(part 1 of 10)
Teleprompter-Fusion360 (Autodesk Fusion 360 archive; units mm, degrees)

design "Teleprompter-Multi" references "Logitech-Brio", "TV-Adapter", "Desklab-Screen"
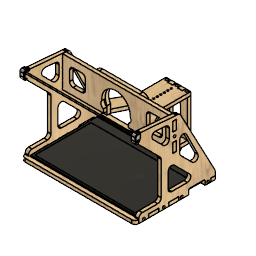
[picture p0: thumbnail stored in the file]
parameter "d305" = 2.5
component_insert "Komponente einfügen1"
position "Position1"
sketch "Skizze1" plane through (0, 0, 0) normal (0, 0, 1) x axis (1, 0, 0)
  dimension "d3" = 15
  dimension "d4" = 15
  dimension "d5" = 15
  dimension "d6" = 30
extrude "Extrusion1" new body sketch "Skizze1" along normal blind 12
sketch "Skizze2" plane through (0, 0, 12) normal (0, 0, 1) x axis (-1, 0, 0)
  line L1 (14.9969, 18.6596) -> (14.9969, -255.3404)
  line L2 (-374.0031, 18.6596) -> (14.9969, 18.6596)
  line L3 (-374.0031, -255.3404) -> (-374.0031, 18.6596)
  line L4 (14.9969, -255.3404) -> (-374.0031, -255.3404)
  line L5 (-3.5031, -225.3404) -> (-355.5031, -225.3404)
  line L6 (-0.0031, 0.1596) -> (-0.0031, -221.8404)
  line L7 (-359.0031, -221.8404) -> (-359.0031, 0.1596)
  line L8 (-355.5031, 3.6596) -> (-3.5031, 3.6596)
  line L9 (-359.0031, -150.3404) -> (-0.0031, -150.3404)
  line L10 (-358.2031, -150.3404) -> (-359.0031, -150.3404)
  line L11 (-0.8031, -150.3404) -> (-358.2031, -150.3404)
  line L12 (-0.0031, -150.3404) -> (-0.8031, -150.3404)
  line L13 (0.9969, 0.1596) -> (0.9969, -221.8404)
  line L14 (-355.5031, 4.6596) -> (-3.5031, 4.6596)
  line L15 (-360.0031, -221.8404) -> (-360.0031, 0.1596)
  line L16 (-3.5031, -226.3404) -> (-355.5031, -226.3404)
  line L17 (-0.0031, -150.3404) -> (-360.0031, -150.3404)
  arc A1 centre (-3.5031, -221.8404) radius 3.5 clockwise from (-0.0031, -221.8404) to (-3.5031, -225.3404)
  arc A2 centre (-355.5031, 0.1596) radius 3.5 clockwise from (-359.0031, 0.1596) to (-355.5031, 3.6596)
  arc A3 centre (-3.5031, 0.1596) radius 3.5 clockwise from (-3.5031, 3.6596) to (-0.0031, 0.1596)
  arc A4 centre (-355.5031, -221.8404) radius 3.5 clockwise from (-355.5031, -225.3404) to (-359.0031, -221.8404)
  arc A5 centre (-3.5031, 0.1596) radius 4.5 clockwise from (-3.5031, 4.6596) to (0.9969, 0.1596)
  arc A6 centre (-355.5031, 0.1596) radius 4.5 clockwise from (-360.0031, 0.1596) to (-355.5031, 4.6596)
  arc A7 centre (-355.5031, -221.8404) radius 4.5 clockwise from (-355.5031, -226.3404) to (-360.0031, -221.8404)
  arc A8 centre (-3.5031, -221.8404) radius 4.5 clockwise from (0.9969, -221.8404) to (-3.5031, -226.3404)
  point P26 (-0.0031, -150.3404)
  point P42 (-0.0031, -150.3404)
  point P43 (-360.0031, -150.3404)
  coincident P26 P42
  coincident L15 P43
  dimension "d7" = 1
extrude "Extrusion2" cut sketch "Skizze2" profile of A1 L5 L6 A2 L7 L8 A3 A4 L9 L10 L11 L12 L13 A5 L14 A6 L16 L15 A7 A8 L17 against normal blind 3
sketch "Skizze3" plane through (0, 0, 9) normal (0, 0, 1) x axis (-1, 0, 0)
  line L1 (-359.0031, -150.3404) -> (-0.0031, -150.3404)
  line L2 (-358.2031, -150.3404) -> (-359.0031, -150.3404)
  line L3 (-0.8031, -150.3404) -> (-358.2031, -150.3404)
  line L4 (-0.0031, -150.3404) -> (-0.8031, -150.3404)
  line L5 (0.9969, 0.1596) -> (0.9969, -221.8404)
  line L6 (-355.5031, 4.6596) -> (-3.5031, 4.6596)
  line L7 (-360.0031, -221.8404) -> (-360.0031, 0.1596)
  line L8 (-3.5031, -226.3404) -> (-355.5031, -226.3404)
  line L9 (0.9969, -150.3404) -> (-0.8031, -150.3404)
  line L10 (-360.0031, -150.3404) -> (-358.2031, -150.3404)
  arc A1 centre (-3.5031, -221.8404) radius 4.5 clockwise from (0.9969, -221.8404) to (-3.5031, -226.3404)
  arc A2 centre (-3.5031, 0.1596) radius 4.5 clockwise from (-3.5031, 4.6596) to (0.9969, 0.1596)
  arc A3 centre (-355.5031, 0.1596) radius 4.5 clockwise from (-360.0031, 0.1596) to (-355.5031, 4.6596)
  arc A4 centre (-355.5031, -221.8404) radius 4.5 clockwise from (-355.5031, -226.3404) to (-360.0031, -221.8404)
  point P18 (-360.0031, -150.3404)
  point P5 (-0.8031, -150.3404)
  point P19 (-0.8031, -150.3404)
  point P20 (0.9969, -150.3404)
  point P4 (-358.2031, -150.3404)
  point P21 (-358.2031, -150.3404)
  coincident L7 P18
  coincident P5 P19
  coincident L5 P20
  perpendicular L5 L9
  coincident P4 P21
  perpendicular L7 L10
extrude "Extrusion3" cut sketch "Skizze3" profile of L1 L2 L3 L4 A1 L5 L7 A4 L8 L9 L10 against normal blind 5
position "Position2"
sketch "Skizze4" plane through (0, 0, 0) normal (1, 0, 0) x axis (0, 1, 0)
  line L1 (255.3404, 0) -> (-18.6596, 0)
  line L2 (255.3404, 12) -> (255.3404, 0)
  line L3 (-18.6596, 12) -> (255.3404, 12)
  line L4 (-18.6596, 0) -> (-18.6596, 12)
  line L5 (-18.6596, 263.0692) -> (232.4096, 12)
  line L6 (532.4096, 12) -> (232.4096, 12)
  line L7 (-18.6596, 263.0692) -> (-18.6596, 12)
  line L8 (-15.8312, 265.8976) -> (235.238, 14.8284)
  line L9 (-15.8312, 265.8976) -> (-18.6596, 263.0692)
  line L10 (237.3593, 7.0503) -> (232.4096, 12)
  line L11 (240.1877, 9.8787) -> (235.238, 14.8284)
  line L12 (240.1877, 9.8787) -> (237.3593, 7.0503)
  point P6 (232.4096, 12)
  point P5 (-18.6596, 12)
  point P8 (-18.6596, 12)
  point P9 (-18.6596, 263.0692)
  point P10 (235.238, 14.8284)
  point P13 (240.1877, 9.8787)
  horizontal L6
  coincident L3 P6
  coincident P5 P8
  perpendicular L3 L7
  parallel L5 L10
  parallel L8 L11
  perpendicular L11 L12
  dimension "d12" angle L5 L6 = 135
  dimension "d14" distance P6 P9 = 355.0654
  dimension "d15" = 4
  dimension "d17" distance P10 P13 = 7
extrude "Extrusion4" new body sketch "Skizze4" profile of L3 L5 L8 L9 L10 L11 L12 to an object offset -8 Side2Offset -8 bodies "Glas"
sketch "Skizze5" plane through (-14.9969, 0, 0) normal (-1, 0, 0) x axis (0, -1, 0)
  line L1 (18.6596, 0) -> (-255.3404, 0)
  line L2 (18.6596, 12) -> (18.6596, 0)
  line L3 (-255.3404, 12) -> (18.6596, 12)
  line L4 (-255.3404, 0) -> (-255.3404, 12)
  line L5 (-225.3404, 14.2) -> (-225.3404, 4.8)
  line L6 (-237.3593, 7.0503) -> (-240.1877, 9.8787)
  line L7 (18.6596, 263.0692) -> (-237.3593, 7.0503)
  line L8 (15.8312, 265.8976) -> (18.6596, 263.0692)
  line L9 (-240.1877, 9.8787) -> (15.8312, 265.8976)
  line L10 (18.6596, 12) -> (-255.3404, 12)
  line L11 (-240.1877, 12) -> (-240.1877, 7.0503)
  line L12 (-232.4096, 7.0503) -> (-232.4096, 12)
  line L13 (-232.4096, 7.0503) -> (-240.1877, 7.0503)
  point P14 (-232.4096, 12)
  point P17 (-240.1877, 12)
  vertical L11
  coincident L10 P14
  coincident L7 P14
  perpendicular L10 L12
  perpendicular L12 L13
  coincident L3 P17
extrude "Extrusion5" cut sketch "Skizze5" profile of L10 L11 L12 L13 against normal blind 430
sketch "Skizze6" plane through (0, 0, 12) normal (0, 0, 1) x axis (-1, 0, 0)
  line L1 (0.9969, -221.8404) -> (0.9969, 0.1596)
  line L2 (-355.5031, -226.3404) -> (-3.5031, -226.3404)
  line L3 (-360.0031, 0.1596) -> (-360.0031, -221.8404)
  line L4 (-3.5031, 4.6596) -> (-355.5031, 4.6596)
  line L5 (14.9969, -232.4096) -> (-374.0031, -232.4096)
  line L6 (14.9969, 18.6596) -> (14.9969, -232.4096)
  line L7 (-374.0031, 18.6596) -> (14.9969, 18.6596)
  line L8 (-374.0031, -232.4096) -> (-374.0031, 18.6596)
  line L9 (14.9969, 18.6596) -> (14.9969, -232.4096)
  line L10 (-366.0031, 18.6596) -> (6.9969, 18.6596)
  line L11 (-374.0031, -232.4096) -> (-374.0031, 18.6596)
  line L12 (14.9969, -255.3404) -> (-374.0031, -255.3404)
  line L13 (2.9969, -255.3404) -> (14.9969, -255.3404)
  line L14 (2.9969, 18.6596) -> (2.9969, -255.3404)
  line L15 (14.9969, 18.6596) -> (2.9969, 18.6596)
  line L16 (14.9969, -255.3404) -> (14.9969, 18.6596)
  arc A1 centre (-3.5031, -221.8404) radius 4.5 clockwise from (0.9969, -221.8404) to (-3.5031, -226.3404)
  arc A2 centre (-355.5031, -221.8404) radius 4.5 clockwise from (-355.5031, -226.3404) to (-360.0031, -221.8404)
  arc A3 centre (-355.5031, 0.1596) radius 4.5 clockwise from (-360.0031, 0.1596) to (-355.5031, 4.6596)
  arc A4 centre (-3.5031, 0.1596) radius 4.5 clockwise from (-3.5031, 4.6596) to (0.9969, 0.1596)
  point P25 (14.9969, -255.3404)
  point P26 (14.9969, -255.3404)
  point P27 (2.9969, -255.3404)
  horizontal L13
  vertical L14
  horizontal L15
  vertical L16
  coincident P25 P26
  dimension "d24" distance P26 P27 = 12
extrude "Extrusion6" new body sketch "Skizze6" profile of L5 L6 L7 L9 L10 L12 L13 L14 L15 L16 along normal blind 255
work_plane "Arbeitsebene1"
sketch "Skizze7" plane through (179.5031, 118.3404, 6) normal (1, 0, 0) x axis (0, 1, 0)
  line L1 (-137, 257.0692) -> (-134.1716, 259.8976)
  line L2 (119.0189, 1.0503) -> (-137, 257.0692)
  line L3 (121.8473, 3.8787) -> (119.0189, 1.0503)
  line L4 (-134.1716, 259.8976) -> (121.8473, 3.8787)
  line L5 (-114.2, 298.1385) -> (-114.2, 9)
  line L6 (78.2, 156.8656) -> (78.2, 9)
  line L7 (78.2, 41.8692) -> (-114.2, 234.2692)
  line L8 (-51.7636, 154.8622) -> (-136.7389, 239.8375)
  line L9 (119.5886, 23.108) -> (-108.8597, 251.5563)
  line L10 (53.128, 21) -> (-12.2488, 21)
  line L11 (114.0692, 6) -> (-137, 6)
  line L12 (-48.2488, 33) -> (-48.2488, 146.3769)
  line L13 (-24.2488, 33) -> (-24.2488, 98.3769)
  line L14 (-136.7389, 239.8375) -> (-136.7389, 21)
  line L15 (61.6133, 41.4853) -> (-3.7636, 106.8622)
  line L16 (-181.5634, 21) -> (-60.2488, 21)
  line L17 (-156.2877, 259.3863) -> (-136.7389, 239.8375)
  line L18 (-156.2877, 5.6722) -> (-156.2877, 259.3863)
  arc A1 centre (-60.2488, 146.3769) radius 12 clockwise from (-51.7636, 154.8622) to (-48.2488, 146.3769)
  arc A2 centre (53.128, 33) radius 12 clockwise from (61.6133, 41.4853) to (53.128, 21)
  arc A3 centre (-12.2488, 98.3769) radius 12 clockwise from (-24.2488, 98.3769) to (-3.7636, 106.8622)
  arc A4 centre (-12.2488, 33) radius 12 clockwise from (-12.2488, 21) to (-24.2488, 33)
  arc A5 centre (-60.2488, 33) radius 12 clockwise from (-48.2488, 33) to (-60.2488, 21)
  point P3 (-114.2, 9)
  point P8 (-114.2, 9)
  point P2 (78.2, 9)
  point P10 (78.2, 9)
  point P12 (-114.2, 234.2692)
  point P13 (78.2, 41.8692)
  point P14 (-50.1361, 170.2053)
  point P19 (-136.7389, 21)
  point P21 (-51.7636, 154.8622)
  point P30 (-12.2488, 21)
  coincident P3 P8
  vertical L5
  coincident P2 P10
  vertical L6
  coincident L5 P12
  coincident L2 P12
  coincident L2 P13
  coincident L6 P13
  coincident L7 P14
  parallel L7 L8
  parallel L4 L9
  horizontal L10
  perpendicular L10 L12
  perpendicular L10 L13
  coincident L10 P19
  perpendicular L10 L14
  tangent L8 A1
  tangent L12 A1
  tangent A1 L15
  tangent L15 A2
  tangent L10 A2
  coincident P21 L15
  tangent L13 A3
  tangent L15 A3
  tangent L10 A4
  tangent L13 A4
  tangent A4 L16
  coincident P30 L16
  tangent L12 A5
  tangent L16 A5
  parallel L8 L17
  perpendicular L16 L18
  dimension "d27" distance P12 P13 = 272.0947
  dimension "d29" distance P12 P14 = 90.6
  dimension "d30" distance L7 L8 = 12
  dimension "d31" distance L4 L9 = 12
  dimension "d32" distance L10 L11 = 15
  dimension "d33" distance L12 L13 = 24
  dimension "d34" radius A1 = 12
  dimension "d35" radius A2 = 12
  dimension "d36" radius A3 = 12
  dimension "d37" radius A4 = 12
  dimension "d38" radius A5 = 12
component_insert "Komponente einfügen2"
extrude "Extrusion7" cut sketch "Skizze7" profile of L8 L10 L12 L13 L14 A1 L15 A2 A3 A4 L16 A5 L17 L18 against normal blind 320
sketch "Skizze10" plane through (-2.9969, 0, 0) normal (1, 0, 0) x axis (0, 1, 0)
  line L1 (66.5768, 160.8622) -> (-18.6596, 246.0986)
  line L2 (70.0916, 39) -> (70.0916, 152.3769)
  line L3 (-18.6596, 27) -> (58.0916, 27)
  line L4 (-18.6596, 12) -> (-18.6596, 27)
  line L5 (255.3404, 12) -> (-18.6596, 12)
  line L6 (255.3404, 267) -> (255.3404, 12)
  line L7 (-18.6596, 267) -> (255.3404, 267)
  line L8 (-18.6596, 246.0986) -> (-18.6596, 267)
  line L9 (94.0916, 104.3769) -> (94.0916, 39)
  line L10 (179.9537, 47.4853) -> (114.5768, 112.8622)
  line L11 (106.0916, 27) -> (171.4684, 27)
  line L12 (94.7, 189.955) -> (94.7, 162.455)
  line L13 (121.7, 162.455) -> (94.7, 162.455)
  line L14 (121.7, 189.955) -> (121.7, 162.455)
  line L15 (94.7, 189.955) -> (121.7, 189.955)
  line L16 (-18.6596, 263.0692) -> (-15.8312, 265.8976)
  line L17 (237.3593, 7.0503) -> (-18.6596, 263.0692)
  line L18 (240.1877, 9.8787) -> (237.3593, 7.0503)
  line L19 (-15.8312, 265.8976) -> (240.1877, 9.8787)
  line L20 (77.2147, 189.8223) -> (-16.1726, 283.2096)
  line L21 (121.7, 244.955) -> (121.7, 150.455)
  line L22 (109.7, 244.955) -> (109.7, 150.455)
  line L23 (121.7, 150.455) -> (109.7, 150.455)
  line L24 (157.7, 189.955) -> (94.7, 189.955)
  line L25 (157.7, 208.955) -> (157.7, 189.955)
  line L26 (94.7, 208.955) -> (157.7, 208.955)
  line L27 (94.7, 189.955) -> (94.7, 208.955)
  line L28 (121.7, 244.955) -> (109.7, 244.955)
  line L29 (133.7, 256.955) -> (133.7, 138.3075)
  line L30 (133.7, 256.955) -> (97.7, 256.955)
  line L31 (97.7, 256.955) -> (97.7, 198.3075)
  line L32 (255.3404, 11.6966) -> (137.2147, 129.8223)
  arc A1 centre (58.0916, 152.3769) radius 12 clockwise from (66.5768, 160.8622) to (70.0916, 152.3769)
  arc A2 centre (58.0916, 39) radius 12 clockwise from (70.0916, 39) to (58.0916, 27)
  arc A3 centre (106.0916, 104.3769) radius 12 clockwise from (94.0916, 104.3769) to (114.5768, 112.8622)
  arc A4 centre (171.4684, 39) radius 12 clockwise from (179.9537, 47.4853) to (171.4684, 27)
  arc A5 centre (106.0916, 39) radius 12 clockwise from (106.0916, 27) to (94.0916, 39)
  arc A6 centre (85.7, 198.3075) radius 12 clockwise from (97.7, 198.3075) to (77.2147, 189.8223)
  arc A7 centre (145.7, 138.3075) radius 12 clockwise from (137.2147, 129.8223) to (133.7, 138.3075)
  point P24 (94.7, 189.955)
  point P34 (94.7, 189.955)
  point P42 (77.2147, 189.8223)
  point P35 (157.7, 189.955)
  point P37 (94.7, 208.955)
  parallel L19 L20
  perpendicular L13 L21
  parallel L21 L22
  perpendicular L22 L23
  horizontal L24
  vertical L25
  horizontal L26
  vertical L27
  coincident P24 P34
  perpendicular L21 L28
  parallel L21 L29
  parallel L28 L30
  parallel L22 L31
  tangent L20 A6
  tangent L31 A6
  tangent A6 L32
  coincident P42 L32
  tangent L29 A7
  tangent L32 A7
  dimension "d41" distance L1 L17 = 12
  dimension "d42" distance L19 L20 = 12
  dimension "d43" distance L21 L22 = 12
  dimension "d44" distance L13 L23 = 12
  dimension "d45" distance P34 P35 = 63
  dimension "d46" distance P34 P37 = 19
  dimension "d47" distance L26 L28 = 36
  dimension "d50" radius A6 = 12
  dimension "d51" radius A7 = 12
extrude "Extrusion8" cut sketch "Skizze10" profile of L5 L6 L7 L20 L29 L30 L31 A6 L32 A7 against normal blind 50
sketch "Skizze11" plane through (0, 0, 9) normal (0, 0, 1) x axis (-1, 0, 0)
  line L1 (0.9969, -150.3404) -> (-360.0031, -150.3404)
  line L2 (0.9969, 0.1596) -> (0.9969, -150.3404)
  line L3 (-355.5031, 4.6596) -> (-3.5031, 4.6596)
  line L4 (-360.0031, -150.3404) -> (-360.0031, 0.1596)
  line L5 (-360.0031, -150.3404) -> (0.9969, -150.3404)
  line L6 (-360.0031, -221.8404) -> (-360.0031, -150.3404)
  line L7 (-3.5031, -226.3404) -> (-355.5031, -226.3404)
  line L8 (0.9969, -150.3404) -> (0.9969, -221.8404)
  line L9 (-324.0031, -114.3404) -> (-324.0031, -31.3404)
  line L10 (-35.0031, -31.3404) -> (-35.0031, -114.3404)
  line L11 (-300.0031, -190.3404) -> (-300.0031, -174.3404)
  line L12 (-59.0031, -174.3404) -> (-59.0031, -190.3404)
  line L13 (-179.5031, 67.0824) -> (-179.5031, -291.9585)
  line L14 (-203.5031, -202.3404) -> (-288.0031, -202.3404)
  line L15 (-71.0031, -202.3404) -> (-155.5031, -202.3404)
  line L16 (-167.5031, -174.3404) -> (-167.5031, -190.3404)
  line L17 (-167.5031, -31.3404) -> (-167.5031, -114.3404)
  line L18 (-191.5031, -174.3404) -> (-191.5031, -190.3404)
  line L19 (-191.5031, -31.3404) -> (-191.5031, -114.3404)
  line L20 (-155.5031, -162.3404) -> (-71.0031, -162.3404)
  line L21 (-288.0031, -162.3404) -> (-203.5031, -162.3404)
  line L22 (-203.5031, -126.3404) -> (-312.0031, -126.3404)
  line L23 (-47.0031, -126.3404) -> (-155.5031, -126.3404)
  line L24 (-155.5031, -19.3404) -> (-47.0031, -19.3404)
  line L25 (-312.0031, -19.3404) -> (-203.5031, -19.3404)
  arc A1 centre (-3.5031, 0.1596) radius 4.5 clockwise from (-3.5031, 4.6596) to (0.9969, 0.1596)
  arc A2 centre (-355.5031, 0.1596) radius 4.5 clockwise from (-360.0031, 0.1596) to (-355.5031, 4.6596)
  arc A3 centre (-355.5031, -221.8404) radius 4.5 clockwise from (-355.5031, -226.3404) to (-360.0031, -221.8404)
  arc A4 centre (-3.5031, -221.8404) radius 4.5 clockwise from (0.9969, -221.8404) to (-3.5031, -226.3404)
  arc A5 centre (-155.5031, -190.3404) radius 12 clockwise from (-155.5031, -202.3404) to (-167.5031, -190.3404)
  arc A6 centre (-155.5031, -174.3404) radius 12 clockwise from (-167.5031, -174.3404) to (-155.5031, -162.3404)
  arc A7 centre (-71.0031, -190.3404) radius 12 clockwise from (-59.0031, -190.3404) to (-71.0031, -202.3404)
  arc A8 centre (-71.0031, -174.3404) radius 12 clockwise from (-71.0031, -162.3404) to (-59.0031, -174.3404)
  arc A9 centre (-203.5031, -190.3404) radius 12 clockwise from (-191.5031, -190.3404) to (-203.5031, -202.3404)
  arc A10 centre (-203.5031, -174.3404) radius 12 clockwise from (-203.5031, -162.3404) to (-191.5031, -174.3404)
  arc A11 centre (-288.0031, -190.3404) radius 12 clockwise from (-288.0031, -202.3404) to (-300.0031, -190.3404)
  arc A12 centre (-288.0031, -174.3404) radius 12 clockwise from (-300.0031, -174.3404) to (-288.0031, -162.3404)
  arc A13 centre (-312.0031, -114.3404) radius 12 clockwise from (-312.0031, -126.3404) to (-324.0031, -114.3404)
  arc A14 centre (-312.0031, -31.3404) radius 12 clockwise from (-324.0031, -31.3404) to (-312.0031, -19.3404)
  arc A15 centre (-203.5031, -31.3404) radius 12 clockwise from (-203.5031, -19.3404) to (-191.5031, -31.3404)
  arc A16 centre (-203.5031, -114.3404) radius 12 clockwise from (-191.5031, -114.3404) to (-203.5031, -126.3404)
  arc A17 centre (-155.5031, -114.3404) radius 12 clockwise from (-155.5031, -126.3404) to (-167.5031, -114.3404)
  arc A18 centre (-155.5031, -31.3404) radius 12 clockwise from (-167.5031, -31.3404) to (-155.5031, -19.3404)
  arc A19 centre (-47.0031, -31.3404) radius 12 clockwise from (-47.0031, -19.3404) to (-35.0031, -31.3404)
  arc A20 centre (-47.0031, -114.3404) radius 12 clockwise from (-35.0031, -114.3404) to (-47.0031, -126.3404)
  parallel L8 L13
  parallel L13 L16
  parallel L6 L11
  parallel L7 L14
  parallel L8 L12
  collinear L14 L15
  collinear L16 L17
  collinear L18 L19
  perpendicular L11 L20
  collinear L20 L21
  parallel L3 L24
  parallel L4 L9
  parallel L1 L22
  parallel L2 L10
  collinear L22 L23
  collinear L24 L25
  tangent L15 A5
  tangent L16 A5
  tangent L16 A6
  tangent L20 A6
  tangent L12 A7
  tangent L15 A7
  tangent L12 A8
  tangent L20 A8
  tangent L18 A9
  tangent L14 A9
  tangent L21 A10
  tangent L18 A10
  tangent L14 A11
  tangent L11 A11
  tangent L11 A12
  tangent L21 A12
  tangent L22 A13
  tangent L9 A13
  tangent L9 A14
  tangent L25 A14
  tangent L25 A15
  tangent L19 A15
  tangent L19 A16
  tangent L22 A16
  tangent L23 A17
  tangent L17 A17
  tangent L17 A18
  tangent L24 A18
  tangent L24 A19
  tangent L10 A19
  tangent L10 A20
  tangent L23 A20
  dimension "d56" distance L6 L8 = 361
  dimension "d57" distance L8 L13 = 180.5 (= "361.00 mm / 2")
  dimension "d60" distance L1 L20 = 12
  dimension "d61" radius A5 = 12
  dimension "d62" radius A6 = 12
  dimension "d63" radius A7 = 12
  dimension "d64" radius A8 = 12
  dimension "d65" radius A9 = 12
  dimension "d66" radius A10 = 12
  dimension "d67" radius A11 = 12
  dimension "d68" radius A12 = 12
  dimension "d69" radius A13 = 12
  dimension "d70" radius A14 = 12
  dimension "d71" radius A15 = 12
  dimension "d72" radius A16 = 12
  dimension "d73" radius A17 = 12
  dimension "d74" radius A18 = 12
  dimension "d75" radius A19 = 12
  dimension "d76" radius A20 = 12
extrude "Extrusion9" cut sketch "Skizze11" profile of L25 L9 L23 L10 L11 L15 L12 L19 L17 L21 A5 A6 A7 A8 A9 A10 A11 A12 A13 A14 A15 A16 A17 A18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 against normal blind 80
sketch "Skizze12" plane through (-2.9969, 0, 0) normal (1, 0, 0) x axis (0, 1, 0)
  line L1 (0.037, 267) -> (77.2147, 189.8223)
  line L2 (-18.6596, 267) -> (0.037, 267)
  line L3 (-18.6596, 246.0986) -> (-18.6596, 267)
  line L4 (66.5768, 160.8622) -> (-18.6596, 246.0986)
  line L5 (70.0916, 39) -> (70.0916, 152.3769)
  line L6 (-18.6596, 27) -> (58.0916, 27)
  line L7 (-18.6596, 12) -> (-18.6596, 27)
  line L8 (255.037, 12) -> (-18.6596, 12)
  line L9 (137.2147, 129.8223) -> (255.037, 12)
  line L10 (133.7, 256.955) -> (133.7, 138.3075)
  line L11 (97.7, 256.955) -> (133.7, 256.955)
  line L12 (97.7, 198.3075) -> (97.7, 256.955)
  line L13 (94.0916, 104.3769) -> (94.0916, 39)
  line L14 (179.9537, 47.4853) -> (114.5768, 112.8622)
  line L15 (106.0916, 27) -> (171.4684, 27)
  line L16 (-18.6596, 263.0692) -> (-15.8312, 265.8976)
  line L17 (237.3593, 7.0503) -> (-18.6596, 263.0692)
  line L18 (240.1877, 9.8787) -> (237.3593, 7.0503)
  line L19 (-15.8312, 265.8976) -> (240.1877, 9.8787)
  line L20 (237.3593, 6.7674) -> (-18.9425, 263.0692)
  line L21 (240.4706, 9.8787) -> (237.3593, 6.7674)
  line L22 (-15.8312, 266.1804) -> (240.4706, 9.8787)
  line L23 (-18.9425, 263.0692) -> (-15.8312, 266.1804)
  line L24 (-24.1904, 268.3171) -> (-18.9425, 263.0692)
  line L25 (-21.2249, 271.5742) -> (-15.8312, 266.1804)
  line L26 (-19.7369, 270.0861) -> (-22.8481, 266.9749)
  arc A1 centre (58.0916, 152.3769) radius 12 clockwise from (66.5768, 160.8622) to (70.0916, 152.3769)
  arc A2 centre (58.0916, 39) radius 12 clockwise from (70.0916, 39) to (58.0916, 27)
  arc A3 centre (145.7, 138.3075) radius 12 clockwise from (137.2147, 129.8223) to (133.7, 138.3075)
  arc A4 centre (85.7, 198.3075) radius 12 clockwise from (97.7, 198.3075) to (77.2147, 189.8223)
  arc A5 centre (106.0916, 104.3769) radius 12 clockwise from (94.0916, 104.3769) to (114.5768, 112.8622)
  arc A6 centre (171.4684, 39) radius 12 clockwise from (179.9537, 47.4853) to (171.4684, 27)
  arc A7 centre (106.0916, 39) radius 12 clockwise from (106.0916, 27) to (94.0916, 39)
  point P41 (-22.8481, 266.9749)
  point P42 (-19.7369, 270.0861)
  perpendicular L23 L25
  parallel L24 L25
  coincident L24 P41
  coincident L25 P42
  perpendicular L25 L26
  dimension "d79" = 0.2
extrude "Extrusion10" cut sketch "Skizze12" profile of L2 L3 L8 L17 L22 L20 L23 L24 L25 L26 against normal blind 4.35
sketch "Skizze13" plane through (-0.9969, 0, 0) normal (1, 0, 0) x axis (0, 1, 0)
  line L1 (-0.1596, 12) -> (221.8404, 12)
  line L2 (-0.1596, 9) -> (-0.1596, 12)
  line L3 (150.3404, 9) -> (-0.1596, 9)
  line L4 (150.3404, 4) -> (150.3404, 9)
  line L5 (221.8404, 4) -> (150.3404, 4)
  line L6 (221.8404, 12) -> (221.8404, 4)
  line L7 (226.3404, 4) -> (226.3404, 12)
  line L8 (226.3404, 12) -> (226.3404, 4)
  line L9 (220.3404, 4) -> (220.3404, 12)
  line L10 (164.3404, 4) -> (164.3404, 12)
  point P10 (220.3404, 12)
  point P11 (220.3404, 4)
  point P12 (164.3404, 12)
  point P13 (164.3404, 4)
  coincident L1 P10
  coincident L5 P11
  perpendicular L5 L9
  coincident L1 P12
  coincident L5 P13
  perpendicular L5 L10
  dimension "d82" distance L7 L9 = 6
  dimension "d83" distance L8 L10 = 62
extrude "Extrusion11" cut sketch "Skizze13" profile of L1 L5 L9 L10 against normal blind 30
sketch "Skizze14" plane through (360.0031, 0, 0) normal (-1, 0, 0) x axis (0, -1, 0)
  line L1 (-221.8404, 12) -> (0.1596, 12)
  line L2 (-221.8404, 4) -> (-221.8404, 12)
  line L3 (-150.3404, 4) -> (-221.8404, 4)
  line L4 (-150.3404, 9) -> (-150.3404, 4)
  line L5 (0.1596, 9) -> (-150.3404, 9)
  line L6 (0.1596, 12) -> (0.1596, 9)
  line L7 (-226.3404, 4) -> (-226.3404, 12)
  line L8 (-226.3404, 12) -> (-226.3404, 4)
  line L9 (-218.3404, -4.6467) -> (-218.3404, 16.3767)
  line L10 (-168.3404, -11.0919) -> (-168.3404, 26.2476)
  parallel L8 L9
  vertical L10
  dimension "d86" distance L8 L9 = 8
  dimension "d87" distance L7 L10 = 58
extrude "Extrusion12" cut sketch "Skizze14" profile of L1 L3 L9 L10 against normal blind 35
sketch "Skizze15" plane through (0, 0, 12) normal (0, 0, -1) x axis (1, 0, 0)
  line L1 (-7.3469, -238.3493) -> (-2.9969, -238.3493)
  line L2 (-7.3469, -232.1267) -> (-7.3469, -238.3493)
  line L3 (-2.9969, -232.1267) -> (-7.3469, -232.1267)
  line L4 (-2.9969, 18.6596) -> (-2.9969, -232.1267)
  line L5 (-14.9969, 18.6596) -> (-2.9969, 18.6596)
  line L6 (-14.9969, -255.037) -> (-14.9969, 18.6596)
  line L7 (-2.9969, -255.037) -> (-14.9969, -255.037)
  line L8 (-2.9969, -238.3493) -> (-2.9969, -255.037)
  line L9 (-0.9969, -220.3404) -> (-14.9969, -220.3404)
  line L10 (-14.9969, -220.3404) -> (-0.9969, -220.3404)
  line L11 (-0.9969, -164.3404) -> (-14.9969, -164.3404)
  line L12 (-14.9969, -164.3404) -> (-0.9969, -164.3404)
  line L13 (-0.9969, -164.3404) -> (-14.9969, -164.3404)
  line L14 (-0.9969, -220.3404) -> (-0.9969, -164.3404)
  line L15 (-14.9969, -220.3404) -> (-0.9969, -220.3404)
  line L16 (-14.9969, -164.3404) -> (-14.9969, -220.3404)
  point P12 (-0.9969, -220.3404)
  point P17 (-0.9969, -220.3404)
  point P13 (-14.9969, -164.3404)
  point P15 (-14.9969, -164.3404)
  horizontal L13
  vertical L14
  horizontal L15
  vertical L16
  coincident P12 P17
  coincident P13 P15
extrude "Extrusion13" cut sketch "Skizze15" profile of L4 L6 L9 L10 L11 L12 L13 L15 L16 against normal blind 4
sketch "Skizze16" plane through (0, -18.6596, 0) normal (0, -1, 0) x axis (1, 0, 0)
  line L1 (-14.9969, 27) -> (-2.9969, 27)
  line L2 (-14.9969, 12) -> (-14.9969, 27)
  line L3 (-2.9969, 12) -> (-14.9969, 12)
  line L4 (-2.9969, 27) -> (-2.9969, 12)
extrude "Extrusion14" cut sketch "Skizze16" against normal blind 12
fillet "Abrundung1" radius 12
fillet "Abrundung2" radius 12
work_plane "Arbeitsebene2" AlongDistance -12
sketch "Skizze17" plane through (-8.9969, 121.7, 191.6313) normal (0, 1, 0) x axis (1, 0, 0)
  line L1 (-6, 191.6313) -> (383, 191.6313)
  line L2 (-6, 179.6313) -> (-6, 191.6313)
  line L3 (383, 179.6313) -> (-6, 179.6313)
  line L4 (383, 191.6313) -> (383, 179.6313)
  line L5 (-6, 179.6313) -> (-6, 61.809)
  line L6 (-6, 53.3237) -> (-6, -53.3237)
  line L7 (-6, 1.809) -> (-6, -75.3687)
  line L8 (6, -53.3237) -> (6, 53.3237)
  line L9 (6, -75.3687) -> (6, 1.809)
  line L10 (6, 61.809) -> (6, 179.6313)
  line L11 (6, 53.3237) -> (6, 61.809)
  line L12 (371, 179.6313) -> (383, 179.6313)
  line L13 (371, -20.3687) -> (371, 179.6313)
  line L14 (383, -20.3687) -> (371, -20.3687)
  line L15 (383, 179.6313) -> (383, -20.3687)
  line L16 (150.7494, 29.1763) -> (226.2494, 29.1763)
  line L17 (226.2494, 1.6763) -> (150.7494, 1.6763)
  line L18 (150.7494, 41.1763) -> (371, 41.1763)
  line L19 (371, -10.3237) -> (6, -10.3237)
  line L20 (6, 41.1763) -> (226.2494, 41.1763)
  line L21 (6, -65.3237) -> (-6, -65.3237)
  line L22 (371, -53.3237) -> (6, -53.3237)
  line L23 (371, -10.3237) -> (371, 41.1763)
  line L24 (371, -53.3237) -> (371, -10.3237)
  arc A1 centre (226.2494, 15.4263) radius 13.75 clockwise from (226.2494, 29.1763) to (226.2494, 1.6763)
  arc A2 centre (150.7494, 15.4263) radius 13.75 clockwise from (150.7494, 1.6763) to (150.7494, 29.1763)
  arc A3 centre (150.7494, 15.4263) radius 25.75 clockwise from (150.7494, -10.3237) to (150.7494, 41.1763)
  arc A4 centre (226.2494, 15.4263) radius 25.75 clockwise from (226.2494, 41.1763) to (226.2494, -10.3237)
  point P5 (383, 179.6313)
  point P18 (383, 179.6313)
  point P34 (371, -10.3237)
  point P32 (226.2494, -10.3237)
  point P35 (6, -10.3237)
  point P36 (6, 41.1763)
  point P37 (371, 41.1763)
  point P28 (226.2494, 41.1763)
  point P13 (6, -53.3237)
  point P40 (6, -53.3237)
  point P19 (371, 179.6313)
  point P21 (383, -20.3687)
  horizontal L12
  vertical L13
  horizontal L14
  vertical L15
  coincident P5 P18
  tangent A3 L19
  perpendicular L8 L19
  parallel L16 L18
  concentric A2 A3
  parallel L17 L19
  concentric A1 A4
  tangent L18 A4
  tangent L18 A3
  tangent L19 A4
  coincident L13 P34
  coincident P32 L19
  coincident L8 P35
  tangent A4 L20
  coincident L8 P36
  coincident L13 P37
  coincident P28 L18
  coincident P13 P40
  perpendicular L8 L22
  perpendicular L22 L24
  dimension "d99" distance P18 P19 = 12
  dimension "d100" distance P18 P21 = 200
extrude "Extrusion15" new body sketch "Skizze17" profile of L8 L9 A1 L16 A2 L17 L18 L20 L22 L23 L24 against normal blind 12
sketch "Skizze18" plane through (0, 121.7, 0) normal (0, 1, 0) x axis (-1, 0, 0)
  line L1 (-141.7525, 189.955) -> (-217.2525, 189.955)
  line L2 (-217.2525, 162.455) -> (-141.7525, 162.455)
  line L3 (2.9969, 150.455) -> (-362.0031, 150.455)
  line L4 (2.9969, 244.955) -> (2.9969, 150.455)
  line L5 (-362.0031, 244.955) -> (2.9969, 244.955)
  line L6 (-362.0031, 150.455) -> (-362.0031, 244.955)
  line L7 (-21.0031, 174.455) -> (-98.617, 174.455)
  line L8 (-21.0031, 232.955) -> (-21.0031, 174.455)
  line L9 (-133.117, 232.955) -> (-21.0031, 232.955)
  line L10 (-338.0031, 186.455) -> (-338.0031, 220.955)
  line L11 (-251.9038, 177.9697) -> (-217.4038, 212.4697)
  line L12 (-112.0616, 232.955) -> (-196.9185, 232.955)
  line L13 (-179.5031, 80.425) -> (-179.5031, 298.91)
  line L14 (-107.1023, 177.9697) -> (-141.6023, 212.4697)
  line L15 (-225.8891, 232.955) -> (-326.0031, 232.955)
  line L16 (-260.3891, 174.455) -> (-326.0031, 174.455)
  arc A1 centre (-141.7525, 176.205) radius 13.75 clockwise from (-141.7525, 189.955) to (-141.7525, 162.455)
  arc A2 centre (-217.2525, 176.205) radius 13.75 clockwise from (-217.2525, 162.455) to (-217.2525, 189.955)
  arc A3 centre (-326.0031, 220.955) radius 12 clockwise from (-338.0031, 220.955) to (-326.0031, 232.955)
  arc A4 centre (-326.0031, 186.455) radius 12 clockwise from (-326.0031, 174.455) to (-338.0031, 186.455)
  arc A5 centre (-133.117, 220.955) radius 12 clockwise from (-141.6023, 212.4697) to (-133.117, 232.955)
  arc A6 centre (-98.617, 186.455) radius 12 clockwise from (-98.617, 174.455) to (-107.1023, 177.9697)
  arc A7 centre (-225.8891, 220.955) radius 12 clockwise from (-225.8891, 232.955) to (-217.4038, 212.4697)
  arc A8 centre (-260.3891, 186.455) radius 12 clockwise from (-251.9038, 177.9697) to (-260.3891, 174.455)
  point P14 (-196.9185, 232.955)
  point P19 (-326.0031, 232.955)
  point P22 (-326.0031, 174.455)
  point P7 (-217.2525, 176.205)
  horizontal L12
  coincident L9 P14
  vertical L13
  parallel L3 L7
  parallel L4 L8
  parallel L5 L9
  parallel L6 L10
  tangent L10 A3
  tangent L9 A3
  tangent L10 A4
  tangent L7 A4
  coincident L9 P19
  tangent L14 A5
  tangent L9 A5
  coincident L7 P22
  tangent L14 A6
  tangent L7 A6
  coincident P14 L15
  coincident P14 L11
  tangent L15 A7
  tangent L11 A7
  tangent L11 A8
  tangent L16 A8
  dimension "d105" angle L11 L12 = 135
  dimension "d106" distance P7 L11 = 25.75 (= "13.75 mm + 12 mm")
  dimension "d107" distance L4 L6 = 365
  dimension "d108" distance L6 L13 = 182.5 (= "365.00 mm / 2")
  dimension "d109" radius A3 = 12
  dimension "d110" radius A4 = 12
  dimension "d111" radius A5 = 12
  dimension "d112" radius A6 = 12
  dimension "d113" radius A7 = 12
  dimension "d114" radius A8 = 12
extrude "Extrusion16" cut sketch "Skizze18" profile of L8 L7 L9 L10 L11 L14 A3 A4 A5 A6 L15 L16 A7 A8 against normal blind 15
fillet "Abrundung3" radius 12
sketch "Skizze19" plane through (0, 121.7, 0) normal (0, 1, 0) x axis (-1, 0, 0)
  line L1 (-98.617, 174.455) -> (-33.0031, 174.455)
  line L2 (-141.6023, 212.4697) -> (-107.1023, 177.9697)
  line L3 (-33.0031, 232.955) -> (-133.117, 232.955)
  line L4 (-21.0031, 186.455) -> (-21.0031, 220.955)
  line L5 (-338.0031, 220.955) -> (-338.0031, 186.455)
  line L6 (-225.8891, 232.955) -> (-326.0031, 232.955)
  line L7 (-251.9038, 177.9697) -> (-217.4038, 212.4697)
  line L8 (-326.0031, 174.455) -> (-260.3891, 174.455)
  line L9 (-141.7525, 189.955) -> (-217.2525, 189.955)
  line L10 (-217.2525, 162.455) -> (-141.7525, 162.455)
  line L11 (2.9969, 150.455) -> (-362.0031, 150.455)
  line L12 (2.9969, 244.955) -> (2.9969, 150.455)
  line L13 (-362.0031, 244.955) -> (2.9969, 244.955)
  line L14 (-362.0031, 150.455) -> (-362.0031, 244.955)
  line L15 (-179.5025, 201.8702) -> (-179.5025, 158.2946)
  line L16 (-161.0025, 189.955) -> (-198.0025, 189.955)
  line L17 (-161.0025, 198.455) -> (-161.0025, 189.955)
  line L18 (-198.0025, 198.455) -> (-161.0025, 198.455)
  line L19 (-198.0025, 189.955) -> (-198.0025, 198.455)
  arc A1 centre (-98.617, 186.455) radius 12 clockwise from (-98.617, 174.455) to (-107.1023, 177.9697)
  arc A2 centre (-133.117, 220.955) radius 12 clockwise from (-141.6023, 212.4697) to (-133.117, 232.955)
  arc A3 centre (-33.0031, 220.955) radius 12 clockwise from (-33.0031, 232.955) to (-21.0031, 220.955)
  arc A4 centre (-33.0031, 186.455) radius 12 clockwise from (-21.0031, 186.455) to (-33.0031, 174.455)
  arc A5 centre (-326.0031, 220.955) radius 12 clockwise from (-338.0031, 220.955) to (-326.0031, 232.955)
  arc A6 centre (-225.8891, 220.955) radius 12 clockwise from (-225.8891, 232.955) to (-217.4038, 212.4697)
  arc A7 centre (-260.3891, 186.455) radius 12 clockwise from (-251.9038, 177.9697) to (-260.3891, 174.455)
  arc A8 centre (-326.0031, 186.455) radius 12 clockwise from (-326.0031, 174.455) to (-338.0031, 186.455)
  arc A9 centre (-141.7525, 176.205) radius 13.75 clockwise from (-141.7525, 189.955) to (-141.7525, 162.455)
  arc A10 centre (-217.2525, 176.205) radius 13.75 clockwise from (-217.2525, 162.455) to (-217.2525, 189.955)
  point P38 (-198.0025, 189.955)
  point P26 (-217.2525, 189.955)
  point P27 (-141.7525, 189.955)
  point P39 (-161.0025, 189.955)
  point P41 (-198.0025, 198.455)
  perpendicular L10 L15
  horizontal L16
  vertical L17
  horizontal L18
  vertical L19
  coincident L9 P38
  dimension "d119" distance P26 P27 = 75.5
  dimension "d120" distance P26 L15 = 37.75 (= "75.50 mm / 2")
  dimension "d121" distance P38 P39 = 37
  dimension "d122" distance P38 P41 = 8.5
  dimension "d123" distance L15 L19 = 18.5 (= "d121 / 2")
extrude "Extrusion17" cut sketch "Skizze19" profile of L9 L15 L16 L17 L18 L19 against normal blind 20
fillet "Abrundung4" radius 4
sketch "Skizze20" plane through (-14.9969, 0, 0) normal (-1, 0, 0) x axis (0, -1, 0)
  line L1 (-94.0916, 39) -> (-94.0916, 104.3769)
  line L2 (-171.4684, 27) -> (-106.0916, 27)
  line L3 (-114.5768, 112.8622) -> (-179.9537, 47.4853)
  line L4 (-121.7, 256.955) -> (-109.7, 256.955)
  line L5 (-133.7, 138.3075) -> (-133.7, 244.955)
  line L6 (-255.037, 12) -> (-137.2147, 129.8223)
  line L7 (-220.3404, 12) -> (-255.037, 12)
  line L8 (-220.3404, 16) -> (-220.3404, 12)
  line L9 (-164.3404, 16) -> (-220.3404, 16)
  line L10 (-164.3404, 12) -> (-164.3404, 16)
  line L11 (6.6596, 12) -> (-164.3404, 12)
  line L12 (6.6596, 15) -> (6.6596, 12)
  line L13 (-58.0916, 27) -> (-5.3404, 27)
  line L14 (-70.0916, 152.3769) -> (-70.0916, 39)
  line L15 (18.6596, 246.0986) -> (-66.5768, 160.8622)
  line L16 (18.6596, 267) -> (18.6596, 246.0986)
  line L17 (-0.037, 267) -> (18.6596, 267)
  line L18 (-77.2147, 189.8223) -> (-0.037, 267)
  line L19 (-97.7, 244.955) -> (-97.7, 198.3075)
  line L20 (-121.7, 256.955) -> (-0.037, 267)
  line L21 (-45.7711, 251.1832) -> (-86.6874, 247.805)
  line L22 (-36.2984, 230.7386) -> (-77.2147, 189.8223)
  line L23 (-97.7, 198.3075) -> (-97.7, 235.8456)
  arc A1 centre (-106.0916, 39) radius 12 clockwise from (-94.0916, 39) to (-106.0916, 27)
  arc A2 centre (-171.4684, 39) radius 12 clockwise from (-171.4684, 27) to (-179.9537, 47.4853)
  arc A3 centre (-106.0916, 104.3769) radius 12 clockwise from (-114.5768, 112.8622) to (-94.0916, 104.3769)
  arc A4 centre (-109.7, 244.955) radius 12 clockwise from (-109.7, 256.955) to (-97.7, 244.955)
  arc A5 centre (-121.7, 244.955) radius 12 clockwise from (-133.7, 244.955) to (-121.7, 256.955)
  arc A6 centre (-145.7, 138.3075) radius 12 clockwise from (-133.7, 138.3075) to (-137.2147, 129.8223)
  arc A7 centre (-5.3404, 15) radius 12 clockwise from (-5.3404, 27) to (6.6596, 15)
  arc A8 centre (-58.0916, 39) radius 12 clockwise from (-58.0916, 27) to (-70.0916, 39)
  arc A9 centre (-58.0916, 152.3769) radius 12 clockwise from (-70.0916, 152.3769) to (-66.5768, 160.8622)
  arc A10 centre (-85.7, 198.3075) radius 12 clockwise from (-77.2147, 189.8223) to (-97.7, 198.3075)
  arc A11 centre (-44.7837, 239.2239) radius 12 clockwise from (-45.7711, 251.1832) to (-36.2984, 230.7386)
  arc A12 centre (-109.7, 244.955) radius 12 clockwise from (-97.8559, 246.8828) to (-97.7, 244.955)
  arc A13 centre (-85.7, 235.8456) radius 12 clockwise from (-97.7, 235.8456) to (-86.6874, 247.805)
  point P37 (-0.037, 267)
  point P41 (-0.037, 267)
  point P14 (-121.7, 256.955)
  point P42 (-121.7, 256.955)
  point P43 (-97.8559, 246.8828)
  point P38 (-77.2147, 189.8223)
  point P44 (-77.2147, 189.8223)
  point P11 (-97.7, 244.955)
  point P48 (-97.7, 244.955)
  coincident P37 P41
  coincident P14 P42
  parallel L20 L21
  coincident A4 P43
  coincident P38 P44
  tangent L21 A11
  tangent L22 A11
  coincident P11 P48
  parallel L19 L23
  tangent L23 A12
  coincident P48 L23
  coincident L21 P43
  tangent L23 A13
  tangent L21 A13
  dimension "d128" distance L20 L21 = 12
  dimension "d129" radius A11 = 12
  dimension "d130" radius A13 = 12
extrude "Extrusion18" add sketch "Skizze20" profile of A4 L4 L18 L19 L20 L21 A11 A12 A13 against normal blind 12
sketch "Skizze21" plane through (-14.9969, 0, 0) normal (-1, 0, 0) x axis (0, -1, 0)
  line L1 (-133.7, 138.3075) -> (-133.7, 244.955)
  line L2 (-255.037, 12) -> (-137.2147, 129.8223)
  line L3 (-220.3404, 12) -> (-255.037, 12)
  line L4 (-220.3404, 16) -> (-220.3404, 12)
  line L5 (-164.3404, 16) -> (-220.3404, 16)
  line L6 (-164.3404, 12) -> (-164.3404, 16)
  line L7 (6.6596, 12) -> (-164.3404, 12)
  line L8 (6.6596, 15) -> (6.6596, 12)
  line L9 (-58.0916, 27) -> (-5.3404, 27)
  line L10 (-70.0916, 152.3769) -> (-70.0916, 39)
  line L11 (18.6596, 246.0986) -> (-66.5768, 160.8622)
  line L12 (18.6596, 267) -> (18.6596, 246.0986)
  line L13 (-0.037, 267) -> (18.6596, 267)
  line L14 (-121.7, 256.955) -> (-0.037, 267)
  line L15 (-94.0916, 39) -> (-94.0916, 104.3769)
  line L16 (-171.4684, 27) -> (-106.0916, 27)
  line L17 (-114.5768, 112.8622) -> (-179.9537, 47.4853)
  line L18 (-45.7711, 251.1832) -> (-86.6874, 247.805)
  line L19 (-77.2147, 189.8223) -> (-36.2984, 230.7386)
  line L20 (-97.7, 235.8456) -> (-97.7, 198.3075)
  line L21 (-126.9563, 256.521) -> (-0.037, 267)
  line L22 (-133.7, 177.9426) -> (-133.7, 138.3075)
  line L23 (-136.7133, 249.9055) -> (-255.037, 12)
  line L24 (-156.4445, 183.2864) -> (-195.6625, 104.4333)
  line L25 (-137.2147, 129.8223) -> (-176.4327, 90.6042)
  arc A1 centre (-121.7, 244.955) radius 12 clockwise from (-133.7, 244.955) to (-121.7, 256.955)
  arc A2 centre (-145.7, 138.3075) radius 12 clockwise from (-133.7, 138.3075) to (-137.2147, 129.8223)
  arc A3 centre (-5.3404, 15) radius 12 clockwise from (-5.3404, 27) to (6.6596, 15)
  arc A4 centre (-58.0916, 39) radius 12 clockwise from (-58.0916, 27) to (-70.0916, 39)
  arc A5 centre (-58.0916, 152.3769) radius 12 clockwise from (-70.0916, 152.3769) to (-66.5768, 160.8622)
  arc A6 centre (-106.0916, 39) radius 12 clockwise from (-94.0916, 39) to (-106.0916, 27)
  arc A7 centre (-171.4684, 39) radius 12 clockwise from (-171.4684, 27) to (-179.9537, 47.4853)
  arc A8 centre (-106.0916, 104.3769) radius 12 clockwise from (-114.5768, 112.8622) to (-94.0916, 104.3769)
  arc A9 centre (-85.7, 235.8456) radius 12 clockwise from (-97.7, 235.8456) to (-86.6874, 247.805)
  arc A10 centre (-44.7837, 239.2239) radius 12 clockwise from (-45.7711, 251.1832) to (-36.2984, 230.7386)
  arc A11 centre (-85.7, 198.3075) radius 12 clockwise from (-77.2147, 189.8223) to (-97.7, 198.3075)
  arc A12 centre (-125.9689, 244.5617) radius 12 clockwise from (-136.7133, 249.9055) to (-126.9563, 256.521)
  arc A13 centre (-145.7, 177.9426) radius 12 clockwise from (-156.4445, 183.2864) to (-133.7, 177.9426)
  arc A14 centre (-184.918, 99.0895) radius 12 clockwise from (-176.4327, 90.6042) to (-195.6625, 104.4333)
  point P25 (-0.037, 267)
  point P44 (-0.037, 267)
  point P5 (-133.7, 138.3075)
  point P45 (-133.7, 138.3075)
  point P8 (-255.037, 12)
  point P46 (-255.037, 12)
  point P6 (-137.2147, 129.8223)
  point P53 (-137.2147, 129.8223)
  coincident P25 P44
  parallel L14 L21
  coincident P5 P45
  tangent A2 L22
  coincident P8 P46
  parallel L23 L24
  tangent L23 A12
  tangent L21 A12
  tangent L24 A13
  tangent L22 A13
  coincident P6 P53
  tangent L25 A14
  tangent L24 A14
  dimension "d133" distance L23 L24 = 12
  dimension "d134" radius A12 = 12
  dimension "d135" radius A13 = 12
  dimension "d136" radius A14 = 12
extrude "Extrusion19" add sketch "Skizze21" profile of A1 L1 L2 L21 L23 L24 A12 A13 A14 against normal blind 12
fillet "Abrundung5" radius 12
fillet "Abrundung6" radius 4
fillet "Abrundung7" radius 12
sketch "Skizze22" plane through (0, 0, 4) normal (0, 0, 1) x axis (-1, 0, 0)
  line L1 (-300.0031, -174.3404) -> (-300.0031, -190.3404)
  line L2 (-203.5031, -162.3404) -> (-288.0031, -162.3404)
  line L3 (-191.5031, -190.3404) -> (-191.5031, -174.3404)
  line L4 (-288.0031, -202.3404) -> (-203.5031, -202.3404)
  line L5 (-155.5031, -202.3404) -> (-71.0031, -202.3404)
  line L6 (-167.5031, -174.3404) -> (-167.5031, -190.3404)
  line L7 (-71.0031, -162.3404) -> (-155.5031, -162.3404)
  line L8 (-59.0031, -190.3404) -> (-59.0031, -174.3404)
  line L9 (-360.0031, -150.3404) -> (0.9969, -150.3404)
  line L10 (-360.0031, -168.3404) -> (-360.0031, -150.3404)
  line L11 (-374.0031, -168.3404) -> (-360.0031, -168.3404)
  line L12 (-374.0031, -218.3404) -> (-374.0031, -168.3404)
  line L13 (-360.0031, -218.3404) -> (-374.0031, -218.3404)
  line L14 (-360.0031, -221.8404) -> (-360.0031, -218.3404)
  line L15 (-3.5031, -226.3404) -> (-355.5031, -226.3404)
  line L16 (0.9969, -220.3404) -> (0.9969, -221.8404)
  line L17 (14.9969, -220.3404) -> (0.9969, -220.3404)
  line L18 (14.9969, -164.3404) -> (14.9969, -220.3404)
  line L19 (0.9969, -164.3404) -> (14.9969, -164.3404)
  line L20 (0.9969, -150.3404) -> (0.9969, -164.3404)
  line L21 (-360.0031, -168.3404) -> (-360.0031, -218.3404)
  arc A1 centre (-288.0031, -174.3404) radius 12 clockwise from (-300.0031, -174.3404) to (-288.0031, -162.3404)
  arc A2 centre (-203.5031, -174.3404) radius 12 clockwise from (-203.5031, -162.3404) to (-191.5031, -174.3404)
  arc A3 centre (-203.5031, -190.3404) radius 12 clockwise from (-191.5031, -190.3404) to (-203.5031, -202.3404)
  arc A4 centre (-288.0031, -190.3404) radius 12 clockwise from (-288.0031, -202.3404) to (-300.0031, -190.3404)
  arc A5 centre (-155.5031, -190.3404) radius 12 clockwise from (-155.5031, -202.3404) to (-167.5031, -190.3404)
  arc A6 centre (-155.5031, -174.3404) radius 12 clockwise from (-167.5031, -174.3404) to (-155.5031, -162.3404)
  arc A7 centre (-71.0031, -174.3404) radius 12 clockwise from (-71.0031, -162.3404) to (-59.0031, -174.3404)
  arc A8 centre (-71.0031, -190.3404) radius 12 clockwise from (-59.0031, -190.3404) to (-71.0031, -202.3404)
  arc A9 centre (-355.5031, -221.8404) radius 4.5 clockwise from (-355.5031, -226.3404) to (-360.0031, -221.8404)
  arc A10 centre (-3.5031, -221.8404) radius 4.5 clockwise from (0.9969, -221.8404) to (-3.5031, -226.3404)
  point P31 (-360.0031, -218.3404)
  point P42 (-360.0031, -218.3404)
  point P28 (-360.0031, -168.3404)
  point P43 (-360.0031, -168.3404)
  coincident P31 P42
  coincident P28 P43
extrude "Extrusion20" cut sketch "Skizze22" profile of L11 L12 L13 L21 against normal blind 8
offset_faces "Flächen versetzen1" distance -2
fillet "Abrundung8" radius 6
fillet "Abrundung9" radius 6
fillet "Abrundung10" radius 6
